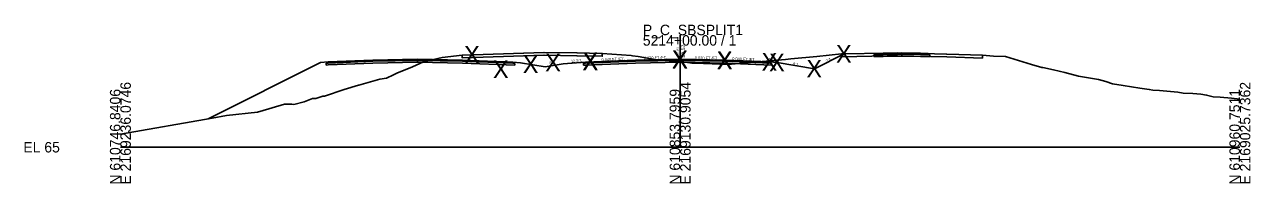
# Model space of a CAD drawing. Extents: x -26 to 1303, y -3010 to 12023.
# Drawn here: x 974.3 to 1302.8, y 8990.3 to 9032.8 of the extents above; entities that cross this region are included whole.
import ezdxf

# ---------------------------------------------------------------- set-up
doc = ezdxf.new("R2010")
doc.units = 0
for name, color, linetype in [('RD_GPK_XS_Cell', 7, 'Continuous'), ('RD_GPK_XS_Text_Node', 7, 'Continuous'), ('RD_XS_Base', 7, 'Continuous'), ('RD_XS_ExGround', 7, 'Continuous'), ('RD_XS_ExPaveRet', 7, 'Continuous'), ('RD_XS_Greenside', 7, 'Continuous'), ('RD_XS_Pave', 7, 'Continuous'), ('RD_XS_PaveOvlay_CP', 7, 'Continuous'), ('RD_XS_TieSlope', 7, 'Continuous'), ('RD_XS_TX_Elev_EX', 7, 'Continuous'), ('RD_XS_TX_Elev_PR', 7, 'Continuous'), ('RD_XS_TX_ShdSlope', 7, 'Continuous'), ('RD_XS_TX_Slope', 7, 'Continuous')]:
    doc.layers.add(name, color=color, linetype=linetype)

msp = doc.modelspace()

# ---------------------------------------------------------------- linework, layer by layer
at = {"layer": 'RD_GPK_XS_Cell'}
for p, q in [((1150, 9000), (1150, 9030)), ((1000, 9000), (1150, 9000)), ((1150, 9000), (1300, 9000))]:
    msp.add_line(p, q, dxfattribs=at)
at = {"layer": 'RD_XS_Base'}
for p, q in [((1202.45, 9024.78), (1204.45, 9024.82)), ((1204.45, 9024.82), (1209.45, 9024.92)), ((1209.45, 9024.98), (1209.45, 9025.08)), ((1209.45, 9025.08), (1209.45, 9024.84)), ((1209.45, 9024.92), (1209.45, 9024.98)), ((1211.25, 9024.88), (1209.45, 9024.92)), ((1209.45, 9024.92), (1209.45, 9024.42)), ((1209.45, 9024.84), (1209.45, 9024.42)), ((1214.45, 9024.82), (1211.25, 9024.88)), ((1215.15, 9024.8), (1214.45, 9024.82)), ((1216.45, 9024.78), (1215.15, 9024.8)), ((1055.64, 9022.53), (1055.14, 9022.51)), ((1055.14, 9022.51), (1055.14, 9022.51)), ((1055.14, 9022.51), (1055.14, 9022.01)), ((1055.14, 9022.01), (1055.64, 9022.03)), ((1055.14, 9022.01), (1055.14, 9022.01)), ((1055.14, 9022.01), (1055.14, 9022.01)), ((1055.69, 9022.53), (1055.64, 9022.53)), ((1055.64, 9022.03), (1055.69, 9022.03)), ((1067.64, 9023.01), (1055.69, 9022.53)), ((1055.69, 9022.03), (1067.64, 9022.51)), ((1067.67, 9023.01), (1067.64, 9023.01)), ((1067.64, 9022.51), (1067.67, 9022.51)), ((1079.64, 9023.25), (1067.67, 9023.01)), ((1067.67, 9022.51), (1079.64, 9022.75)), ((1079.64, 9022.75), (1079.64, 9023.41)), ((1079.64, 9023.41), (1079.64, 9023.25)), ((1079.64, 9023.25), (1079.64, 9023.41)), ((1079.64, 9023.41), (1079.64, 9023.41)), ((1079.64, 9023.41), (1079.64, 9023.41)), ((1079.64, 9023.41), (1079.64, 9022.75)), ((1079.64, 9022.75), (1079.64, 9023.25)), ((1079.64, 9023.25), (1079.64, 9023.25)), ((1079.64, 9022.75), (1079.64, 9023.25)), ((1079.64, 9023.25), (1079.64, 9023.25)), ((1079.64, 9023.25), (1079.64, 9023.25)), ((1079.64, 9023.25), (1079.64, 9023.25)), ((1091.64, 9023.01), (1079.64, 9023.25)), ((1079.64, 9022.75), (1079.64, 9022.75)), ((1079.64, 9022.75), (1079.64, 9022.75)), ((1079.64, 9022.75), (1079.64, 9022.75)), ((1079.64, 9022.75), (1079.64, 9022.75)), ((1079.64, 9022.75), (1091.64, 9022.51)), ((1105.19, 9022.47), (1091.64, 9023.01)), ((1091.64, 9022.51), (1105.69, 9021.95)), ((1093.64, 9022.93), (1093.64, 9022.93)), ((1093.64, 9022.43), (1093.64, 9022.43)), ((1105.69, 9022.45), (1105.19, 9022.47)), ((1105.19, 9022.47), (1105.19, 9022.47)), ((1105.69, 9021.95), (1105.69, 9022.45)), ((1105.69, 9022.45), (1105.69, 9022.45)), ((1124.61, 9022.48), (1124.11, 9022.46)), ((1124.11, 9022.46), (1124.11, 9022.46)), ((1124.11, 9022.46), (1124.11, 9021.96)), ((1124.11, 9021.96), (1124.61, 9021.98)), ((1138, 9023.01), (1124.61, 9022.48)), ((1124.61, 9021.98), (1138, 9022.51)), ((1124.61, 9022.48), (1124.61, 9022.48)), ((1124.61, 9021.98), (1124.61, 9021.98)), ((1150, 9023.25), (1138, 9023.01)), ((1138, 9022.51), (1150, 9022.75)), ((1150, 9022.75), (1150, 9023.41)), ((1150, 9023.41), (1150, 9023.41)), ((1150, 9023.41), (1150, 9023.41)), ((1150, 9023.41), (1150, 9023.25)), ((1150, 9022.75), (1150, 9023.25)), ((1150, 9023.25), (1150, 9023.25)), ((1150, 9023.25), (1150, 9023.25)), ((1150, 9023.25), (1150, 9023.25)), ((1150, 9023.25), (1162, 9023.01)), ((1150, 9023.25), (1150, 9023.25)), ((1150, 9022.75), (1150, 9022.75)), ((1162, 9022.51), (1150, 9022.75)), ((1150, 9022.75), (1150, 9022.75)), ((1162, 9023.01), (1162, 9023.01)), ((1162, 9023.01), (1174, 9022.53)), ((1174.5, 9022.01), (1162, 9022.51)), ((1162, 9022.51), (1162, 9022.51)), ((1174, 9022.53), (1174, 9022.53)), ((1174, 9022.53), (1174.5, 9022.51)), ((1174.5, 9022.51), (1174.5, 9022.51)), ((1174.5, 9022.51), (1174.5, 9022.01)), ((1201.95, 9024.77), (1202.45, 9024.78)), ((1201.95, 9024.27), (1201.95, 9024.77)), ((1202.45, 9024.28), (1201.95, 9024.27)), ((1204.45, 9024.32), (1202.45, 9024.28)), ((1209.45, 9024.42), (1204.45, 9024.32)), ((1209.45, 9024.42), (1211.25, 9024.38)), ((1211.25, 9024.38), (1214.45, 9024.32)), ((1214.45, 9024.32), (1215.32, 9024.3)), ((1215.32, 9024.3), (1216.95, 9024.27)), ((1216.62, 9024.78), (1216.45, 9024.78)), ((1216.95, 9024.77), (1216.62, 9024.78)), ((1216.95, 9024.6), (1216.95, 9024.77)), ((1216.95, 9024.27), (1216.95, 9024.6))]:
    msp.add_line(p, q, dxfattribs=at)
at = {"layer": 'RD_XS_ExGround'}
msp.add_lwpolyline([(1000, 9003.49), (1024.59, 9007.82), (1028.4, 9008.47), (1036.78, 9009.39), (1039.74, 9010.24), (1040.64, 9010.58), (1043.97, 9011.51), (1045.18, 9011.57), (1045.91, 9011.51), (1046.47, 9011.47), (1049.29, 9012.18), (1051.49, 9013.03), (1052.34, 9013.02), (1054.27, 9013.63), (1054.73, 9013.66), (1060.01, 9015.45), (1063.81, 9016.58), (1063.82, 9016.58), (1063.83, 9016.58), (1063.9, 9016.6), (1069.55, 9018.18), (1071.35, 9018.52), (1073.22, 9019.4), (1074.07, 9019.79), (1078.24, 9021.5), (1081.25, 9022.86), (1086.27, 9023.98), (1091.63, 9024.65), (1097.25, 9024.84), (1113.54, 9025.39), (1122.34, 9025.24), (1129.14, 9025.11), (1136.85, 9024.53), (1137.21, 9024.5), (1138.76, 9024.27), (1143.25, 9023.51), (1147.04, 9023.13), (1151.95, 9022.66), (1153.09, 9022.54), (1153.98, 9022.48), (1158.59, 9022.34), (1162.7, 9022.15), (1177.18, 9023.42), (1178.21, 9023.5), (1179.63, 9023.65), (1186.62, 9024.32), (1193.26, 9024.98), (1205.52, 9025.21), (1208.25, 9025.26), (1221.44, 9024.91), (1230.99, 9024.63), (1233.96, 9024.42), (1237.23, 9024.31), (1244.12, 9022.13), (1246.91, 9021.36), (1247.15, 9021.36), (1250.05, 9020.73), (1253.07, 9019.97), (1256.77, 9019.02), (1262.09, 9018.09), (1264.08, 9017.56), (1265.88, 9016.94), (1268.74, 9016.5), (1273.23, 9015.82), (1275.69, 9015.5), (1276.68, 9015.28), (1278.46, 9015.18), (1283.36, 9014.76), (1284.82, 9014.5), (1287.42, 9014.38), (1289.52, 9014.17), (1291.06, 9013.95), (1292.81, 9013.5), (1294.74, 9013.4), (1297.74, 9013.13), (1300, 9012.91)], dxfattribs=at)
at = {"layer": 'RD_XS_ExPaveRet'}
for points in [[(1129.14, 9025.11), (1129.14, 9025.11), (1129.14, 9024.37), (1129.14, 9024.36), (1129.14, 9024.36), (1129.14, 9024.36), (1122.41, 9024.49), (1122.34, 9024.49), (1113.57, 9024.63), (1113.54, 9024.64), (1113.48, 9024.63), (1097.25, 9024.09), (1097.22, 9024.09), (1091.63, 9023.9), (1091.63, 9023.9), (1091.63, 9023.9), (1091.63, 9023.91), (1091.63, 9024.65), (1091.63, 9024.65), (1091.63, 9024.65), (1097.22, 9024.84), (1097.25, 9024.84), (1113.48, 9025.38), (1113.54, 9025.39), (1113.57, 9025.38), (1122.34, 9025.24), (1122.41, 9025.24), (1129.14, 9025.11), (1129.14, 9025.11)], [(1129.14, 9025.11), (1122.41, 9025.24), (1122.34, 9025.24), (1113.57, 9025.38), (1113.54, 9025.39), (1113.48, 9025.38), (1097.25, 9024.84), (1097.22, 9024.84), (1091.63, 9024.65), (1091.63, 9023.91), (1091.63, 9023.9), (1097.22, 9024.09), (1097.25, 9024.09), (1113.48, 9024.63), (1113.54, 9024.64), (1113.57, 9024.63), (1122.34, 9024.49), (1122.41, 9024.49), (1129.14, 9024.36), (1129.14, 9024.36), (1129.14, 9024.37), (1129.14, 9025.11), (1129.14, 9025.11)], [(1230.99, 9024.63), (1221.44, 9024.91), (1221.44, 9024.91), (1208.25, 9025.26), (1208.25, 9025.26), (1208.25, 9025.26), (1205.52, 9025.21), (1205.52, 9025.21), (1193.26, 9024.98), (1193.26, 9024.98), (1193.26, 9024.98), (1193.26, 9024.23), (1193.26, 9024.23), (1205.52, 9024.46), (1205.52, 9024.46), (1208.25, 9024.51), (1208.25, 9024.51), (1208.25, 9024.51), (1221.44, 9024.16), (1221.44, 9024.16), (1230.99, 9023.88), (1230.99, 9023.88), (1230.99, 9024.63), (1230.99, 9024.63), (1230.99, 9024.63)], [(1230.99, 9024.63), (1221.44, 9024.91), (1208.25, 9025.26), (1205.52, 9025.21), (1193.26, 9024.98), (1193.26, 9024.98), (1193.26, 9024.23), (1193.26, 9024.23), (1205.52, 9024.46), (1208.25, 9024.51), (1221.44, 9024.16), (1230.99, 9023.88), (1230.99, 9024.63)]]:
    msp.add_lwpolyline(points, dxfattribs=at)
at = {"layer": 'RD_XS_Greenside'}
for p, q in [((1186, 9021.02), (1193.93, 9024.99)), ((1053.64, 9022.69), (1023.52, 9007.63)), ((1107.19, 9022.63), (1113.84, 9021.52)), ((1118.61, 9022.31), (1113.84, 9021.52)), ((1176, 9022.69), (1186, 9021.02))]:
    msp.add_line(p, q, dxfattribs=at)
at = {"layer": 'RD_XS_Pave'}
for p, q in [((1203.22, 9025.11), (1202.45, 9025.1)), ((1202.45, 9025.1), (1202.45, 9025)), ((1202.45, 9025), (1202.45, 9024.94)), ((1204.45, 9024.98), (1202.45, 9024.94)), ((1202.45, 9024.94), (1203.22, 9024.95)), ((1202.45, 9024.94), (1202.45, 9024.78)), ((1202.45, 9024.78), (1204.45, 9024.82)), ((1204.45, 9025.14), (1203.22, 9025.11)), ((1203.22, 9024.95), (1204.45, 9024.98)), ((1206.32, 9025.17), (1204.45, 9025.14)), ((1209.45, 9025.08), (1204.45, 9024.98)), ((1204.45, 9024.98), (1206.32, 9025.02)), ((1204.45, 9024.82), (1209.45, 9024.92)), ((1209.45, 9025.24), (1206.32, 9025.17)), ((1206.32, 9025.02), (1209.45, 9025.08)), ((1211.25, 9025.2), (1209.45, 9025.24)), ((1209.45, 9025.08), (1211.25, 9025.04)), ((1214.45, 9024.98), (1209.45, 9025.08)), ((1209.45, 9025.08), (1209.45, 9024.92)), ((1209.45, 9024.92), (1209.45, 9025.08)), ((1209.45, 9024.92), (1214.45, 9024.82)), ((1214.45, 9025.14), (1211.25, 9025.2)), ((1211.25, 9025.04), (1214.45, 9024.98)), ((1215.15, 9025.12), (1214.45, 9025.14)), ((1214.45, 9024.98), (1215.15, 9024.96)), ((1216.45, 9024.94), (1214.45, 9024.98)), ((1214.45, 9024.82), (1216.45, 9024.78)), ((1216.45, 9025.1), (1215.15, 9025.12)), ((1215.15, 9024.96), (1216.45, 9024.94)), ((1216.45, 9024.99), (1216.45, 9025.1)), ((1216.45, 9024.94), (1216.45, 9024.99)), ((1216.45, 9024.78), (1216.45, 9024.94)), ((1055.69, 9022.85), (1055.64, 9022.85)), ((1055.64, 9022.85), (1055.64, 9022.69)), ((1055.69, 9022.69), (1055.64, 9022.69)), ((1055.64, 9022.69), (1055.64, 9022.53)), ((1055.64, 9022.69), (1055.64, 9022.69)), ((1055.64, 9022.69), (1055.69, 9022.69)), ((1055.64, 9022.53), (1055.64, 9022.53)), ((1055.64, 9022.53), (1055.69, 9022.53)), ((1067.64, 9023.33), (1055.69, 9022.85)), ((1067.64, 9023.17), (1055.69, 9022.69)), ((1055.69, 9022.69), (1067.64, 9023.17)), ((1055.69, 9022.53), (1067.64, 9023.01)), ((1067.67, 9023.33), (1067.64, 9023.33)), ((1067.67, 9023.17), (1067.64, 9023.17)), ((1067.64, 9023.17), (1067.67, 9023.17)), ((1067.64, 9023.01), (1067.67, 9023.01)), ((1079.64, 9023.57), (1067.67, 9023.33)), ((1079.64, 9023.41), (1067.67, 9023.17)), ((1067.67, 9023.17), (1079.64, 9023.41)), ((1067.67, 9023.01), (1079.64, 9023.25)), ((1091.64, 9023.33), (1079.64, 9023.57)), ((1079.64, 9023.57), (1079.64, 9023.57)), ((1079.64, 9023.57), (1079.64, 9023.57)), ((1079.64, 9023.25), (1079.64, 9023.41)), ((1079.64, 9023.25), (1079.64, 9023.41)), ((1079.64, 9023.25), (1079.64, 9023.41)), ((1079.64, 9023.41), (1079.64, 9023.41)), ((1079.64, 9023.41), (1079.64, 9023.41)), ((1079.64, 9023.41), (1079.64, 9023.41)), ((1079.64, 9023.41), (1079.64, 9023.41)), ((1079.64, 9023.41), (1091.64, 9023.17)), ((1091.64, 9023.17), (1079.64, 9023.41)), ((1079.64, 9023.41), (1079.64, 9023.41)), ((1079.64, 9023.41), (1079.64, 9023.41)), ((1079.64, 9023.41), (1079.64, 9023.25)), ((1079.64, 9023.25), (1079.64, 9023.25)), ((1079.64, 9023.25), (1079.64, 9023.25)), ((1079.64, 9023.25), (1079.64, 9023.25)), ((1079.64, 9023.25), (1079.64, 9023.25)), ((1079.64, 9023.25), (1091.64, 9023.01)), ((1105.19, 9022.79), (1091.64, 9023.33)), ((1091.64, 9023.17), (1105.19, 9022.63)), ((1105.19, 9022.63), (1091.64, 9023.17)), ((1091.64, 9023.01), (1105.19, 9022.47)), ((1093.64, 9023.25), (1093.64, 9023.25)), ((1093.64, 9023.09), (1093.64, 9023.09)), ((1093.64, 9023.09), (1093.64, 9023.09)), ((1093.64, 9022.93), (1093.64, 9022.93)), ((1105.19, 9022.63), (1105.19, 9022.79)), ((1105.19, 9022.79), (1105.19, 9022.79)), ((1105.19, 9022.47), (1105.19, 9022.63)), ((1105.19, 9022.63), (1105.19, 9022.63)), ((1138, 9023.33), (1124.61, 9022.79)), ((1138, 9023.17), (1124.61, 9022.64)), ((1124.61, 9022.64), (1138, 9023.17)), ((1124.61, 9022.48), (1138, 9023.01)), ((1124.61, 9022.79), (1124.61, 9022.79)), ((1124.61, 9022.79), (1124.61, 9022.64)), ((1124.61, 9022.64), (1124.61, 9022.64)), ((1124.61, 9022.64), (1124.61, 9022.48)), ((1150, 9023.57), (1138, 9023.33)), ((1150, 9023.41), (1138, 9023.17)), ((1138, 9023.17), (1150, 9023.41)), ((1138, 9023.01), (1150, 9023.25)), ((1162, 9023.33), (1150, 9023.57)), ((1150, 9023.57), (1150, 9023.57)), ((1150, 9023.57), (1150, 9023.57)), ((1150, 9023.25), (1150, 9023.41)), ((1150, 9023.41), (1150, 9023.41)), ((1150, 9023.41), (1150, 9023.41)), ((1150, 9023.41), (1150, 9023.41)), ((1150, 9023.41), (1150, 9023.41)), ((1150, 9023.41), (1162, 9023.17)), ((1162, 9023.17), (1150, 9023.41)), ((1150, 9023.41), (1150, 9023.41)), ((1150, 9023.41), (1150, 9023.41)), ((1150, 9023.41), (1150, 9023.41)), ((1150, 9023.41), (1150, 9023.25)), ((1150, 9023.25), (1150, 9023.25)), ((1150, 9023.25), (1150, 9023.25)), ((1150, 9023.25), (1150, 9023.25)), ((1150, 9023.25), (1162, 9023.01)), ((1174, 9022.85), (1162, 9023.33)), ((1162, 9023.33), (1162, 9023.33)), ((1162, 9023.17), (1162, 9023.17)), ((1162, 9023.17), (1174, 9022.69)), ((1174, 9022.69), (1162, 9023.17)), ((1162, 9023.17), (1162, 9023.17)), ((1162, 9023.01), (1174, 9022.53)), ((1162, 9023.01), (1162, 9023.01)), ((1174, 9022.69), (1174, 9022.85)), ((1174, 9022.85), (1174, 9022.85)), ((1174, 9022.53), (1174, 9022.69)), ((1174, 9022.69), (1174, 9022.69))]:
    msp.add_line(p, q, dxfattribs=at)
at = {"layer": 'RD_XS_PaveOvlay_CP'}
for p, q in [((1202.45, 9025.1), (1204.45, 9025.14)), ((1204.45, 9025.14), (1209.45, 9025.24)), ((1209.45, 9025.24), (1214.45, 9025.14)), ((1214.45, 9025.14), (1216.45, 9025.1)), ((1055.64, 9022.85), (1067.64, 9023.33)), ((1067.64, 9023.33), (1079.64, 9023.57)), ((1079.64, 9023.57), (1091.64, 9023.33)), ((1091.64, 9023.33), (1105.19, 9022.79)), ((1138, 9023.33), (1124.61, 9022.79)), ((1150, 9023.57), (1138, 9023.33)), ((1162, 9023.33), (1150, 9023.57)), ((1150, 9023.57), (1150, 9023.57)), ((1150, 9023.57), (1150, 9023.57)), ((1174, 9022.85), (1162, 9023.33)), ((1162, 9023.33), (1162, 9023.33))]:
    msp.add_line(p, q, dxfattribs=at)
at = {"layer": 'RD_XS_TieSlope'}
for p, q in [((1055.64, 9022.85), (1053.64, 9022.69)), ((1105.19, 9022.79), (1107.19, 9022.63)), ((1124.61, 9022.79), (1118.61, 9022.31)), ((1174, 9022.85), (1176, 9022.69))]:
    msp.add_line(p, q, dxfattribs=at)

# ---------------------------------------------------------------- texts
at = {"layer": 'RD_GPK_XS_Cell'}
for s, p in [('P_C_SBSPLIT1', (1140, 9030)), ('5214+00.00 / 1', (1140, 9027.2)), ('EL 65', (974, 8998.6))]:
    msp.add_text(s, height=2.8, dxfattribs=at).set_placement(p)
for s, p in [('N 610746.8406', (1000, 8990)), ('E 2169236.0746', (1002.8, 8990)), ('N 610853.7959', (1150, 8990)), ('E 2169130.9054', (1152.8, 8990)), ('N 610960.7511', (1300, 8990)), ('E 2169025.7362', (1302.8, 8990))]:
    msp.add_text(s, height=2.8, rotation=90, dxfattribs=at).set_placement(p)
at = {"layer": 'RD_GPK_XS_Text_Node'}
for p in [(1092.1, 9022.4), (1092.13, 9022.4), (1113.84, 9020.35), (1123.84, 9020.75), (1123.84, 9020.59), (1147.84, 9021.23), (1147.84, 9021.07), (1159.84, 9020.99), (1159.84, 9020.83), (1171.84, 9020.51), (1173.84, 9020.35), (1191.77, 9022.65), (1099.84, 9018.53), (1099.86, 9018.53), (1107.84, 9019.87), (1107.86, 9019.87), (1183.84, 9018.68)]:
    msp.add_text('X', height=4.69, dxfattribs=at).set_placement(p)
at = {"layer": 'RD_XS_TX_Elev_EX'}
msp.add_text('87.83', height=0.6, rotation=90, dxfattribs=at).set_placement((1149.63, 9024.67))
at = {"layer": 'RD_XS_TX_Elev_PR'}
msp.add_text('88.57', height=1, rotation=90, dxfattribs=at).set_placement((1151.33, 9024.02))
at = {"layer": 'RD_XS_TX_ShdSlope'}
for rotation, p in [(4.5739, (1120.76, 9022.66)), (355.4261, (1173.71, 9023.13))]:
    msp.add_text('12.5:1', height=0.75, rotation=rotation, dxfattribs=at).set_placement(p)
at = {"layer": 'RD_XS_TX_Slope'}
for s, rotation, p in [('6:1', 9.4642, (1115.01, 9022.18)), ('0.040 FT./FT.', 2.2906, (1128.93, 9023.04)), ('0.020 FT./FT.', 1.1458, (1140.27, 9023.52)), ('0.020 FT./FT.', 358.8542, (1153.94, 9023.57)), ('0.040 FT./FT.', 357.7094, (1163.94, 9023.33)), ('6:1', 350.5358, (1180.2, 9022.02)), ('2:1', 26.5651, (1189.25, 9022.69))]:
    msp.add_text(s, height=0.75, rotation=rotation, dxfattribs=at).set_placement(p)

doc.saveas('drawing.dxf')
